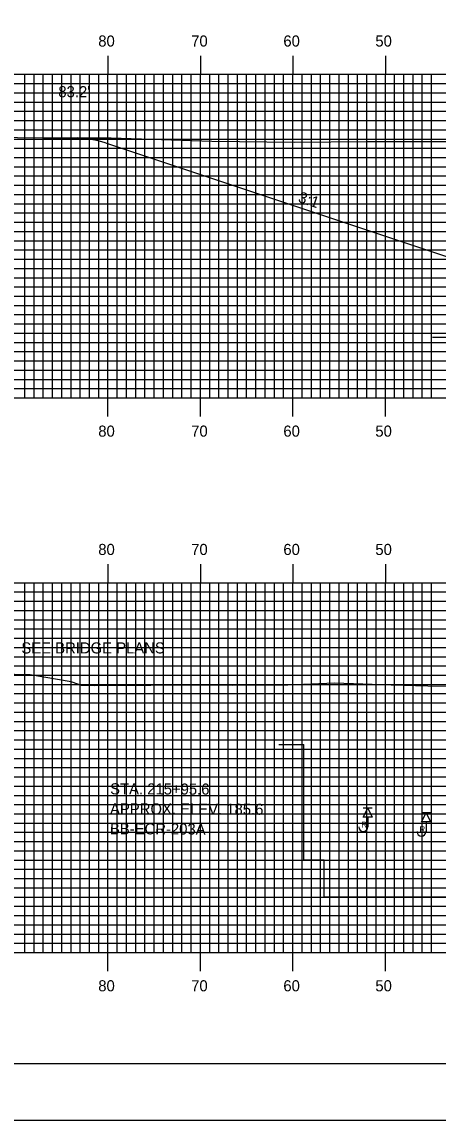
# Model space of a CAD drawing. Extents: x 1796420 to 1796763, y 442591 to 442811.
# Drawn here: x 1796496.6 to 1796541.6, y 442590.5 to 442709.3 of the extents above; entities that cross this region are included whole.
import ezdxf

# ---------------------------------------------------------------- set-up
doc = ezdxf.new("R2010")
doc.units = 0
for name, color, linetype in [('ANNOTATION', 7, 'Continuous'), ('BORDER', 7, 'Continuous'), ('BORING - REFUSAL', 7, 'Continuous'), ('D_Roadway_SlopeLines', 7, 'Continuous'), ('D_Text_Standard', 7, 'Continuous'), ('H_V ANNOTATION', 7, 'Continuous'), ('MAJOR', 7, 'Continuous'), ('MINOR', 7, 'Continuous'), ('PDRAIN', 7, 'Continuous'), ('PLOT BOUNDARY', 7, 'Continuous'), ('S_Roadway_Centerline', 7, 'Continuous')]:
    doc.layers.add(name, color=color, linetype=linetype)

msp = doc.modelspace()

# ---------------------------------------------------------------- linework, layer by layer
at = {"layer": 'ANNOTATION'}
for p, q in [((1796527.11, 442618.67), (1796527.11, 442631.17)), ((1796529.31, 442618.67), (1796527.11, 442618.67)), ((1796529.31, 442614.67), (1796529.31, 442618.67)), ((1796551.73, 442614.67), (1796529.31, 442614.67))]:
    msp.add_line(p, q, dxfattribs=at)
msp.add_lwpolyline([(1796524.4, 442631.17), (1796527.11, 442631.17)], dxfattribs=at)
at = {"layer": 'BORDER'}
msp.add_lwpolyline([(1796436.31, 442596.67), (1796756.31, 442596.67), (1796756.31, 442806.67), (1796436.31, 442806.67)], close=True, dxfattribs=at)
at = {"layer": 'BORING - REFUSAL'}
for p, q in [((1796534.49, 442624.27), (1796533.53, 442624.27)), ((1796534.01, 442623.31), (1796534.01, 442622.25)), ((1796540.79, 442623.77), (1796539.83, 442623.77)), ((1796540.31, 442622.81), (1796540.31, 442621.75))]:
    msp.add_line(p, q, dxfattribs=at)
for points in [[(1796534.01, 442624.27), (1796534.49, 442623.31), (1796533.53, 442623.31)], [(1796540.31, 442623.77), (1796540.79, 442622.81), (1796539.83, 442622.81)]]:
    msp.add_lwpolyline(points, close=True, dxfattribs=at)
for centre in [(1796533.52, 442622.25), (1796539.82, 442621.75)]:
    msp.add_arc(centre, 0.485, 180, 0, dxfattribs=at)
at = {"layer": 'D_Roadway_SlopeLines'}
msp.add_lwpolyline([(1796549.65, 442683.57), (1796543.65, 442683.57), (1796505.9, 442696.15)], dxfattribs=at)
msp.add_arc((1796501.86, 442684.01), 12.8, 71.5651, 86.7573, dxfattribs=at)
at = {"layer": 'MAJOR'}
for p, q in [((1796505.91, 442705.67), (1796505.91, 442703.67)), ((1796515.91, 442705.67), (1796515.91, 442703.67)), ((1796525.91, 442705.67), (1796525.91, 442703.67)), ((1796535.91, 442705.67), (1796535.91, 442703.67)), ((1796445.91, 442703.67), (1796725.91, 442703.67)), ((1796445.91, 442703.67), (1796725.91, 442703.67)), ((1796505.91, 442668.67), (1796505.91, 442703.67)), ((1796515.91, 442668.67), (1796515.91, 442703.67)), ((1796525.91, 442668.67), (1796525.91, 442703.67)), ((1796535.91, 442668.67), (1796535.91, 442703.67)), ((1796445.91, 442698.67), (1796725.91, 442698.67)), ((1796445.91, 442693.67), (1796725.91, 442693.67)), ((1796445.91, 442688.67), (1796725.91, 442688.67)), ((1796445.91, 442683.67), (1796725.91, 442683.67)), ((1796445.91, 442678.67), (1796725.91, 442678.67)), ((1796445.91, 442673.67), (1796725.91, 442673.67)), ((1796445.91, 442668.67), (1796725.91, 442668.67)), ((1796445.91, 442668.67), (1796725.91, 442668.67)), ((1796505.91, 442666.66), (1796505.91, 442668.67)), ((1796515.91, 442666.66), (1796515.91, 442668.67)), ((1796525.91, 442666.66), (1796525.91, 442668.67)), ((1796535.91, 442666.66), (1796535.91, 442668.67)), ((1796505.91, 442650.67), (1796505.91, 442648.67)), ((1796515.91, 442650.67), (1796515.91, 442648.67)), ((1796525.91, 442650.67), (1796525.91, 442648.67)), ((1796535.91, 442650.67), (1796535.91, 442648.67)), ((1796445.91, 442648.67), (1796725.91, 442648.67)), ((1796445.91, 442648.67), (1796725.91, 442648.67)), ((1796505.91, 442608.67), (1796505.91, 442648.67)), ((1796515.91, 442608.67), (1796515.91, 442648.67)), ((1796525.91, 442608.67), (1796525.91, 442648.67)), ((1796535.91, 442608.67), (1796535.91, 442648.67)), ((1796445.91, 442643.67), (1796725.91, 442643.67)), ((1796445.91, 442638.67), (1796725.91, 442638.67)), ((1796445.91, 442633.67), (1796725.91, 442633.67)), ((1796445.91, 442628.67), (1796725.91, 442628.67)), ((1796445.91, 442623.67), (1796725.91, 442623.67)), ((1796445.91, 442618.67), (1796725.91, 442618.67)), ((1796445.91, 442613.67), (1796725.91, 442613.67)), ((1796445.91, 442608.67), (1796725.91, 442608.67)), ((1796445.91, 442608.67), (1796725.91, 442608.67)), ((1796505.91, 442606.66), (1796505.91, 442608.67)), ((1796515.91, 442606.66), (1796515.91, 442608.67)), ((1796525.91, 442606.66), (1796525.91, 442608.67)), ((1796535.91, 442606.66), (1796535.91, 442608.67))]:
    msp.add_line(p, q, dxfattribs=at)
at = {"layer": 'MINOR'}
for p, q in [((1796445.91, 442702.67), (1796725.91, 442702.67)), ((1796496.91, 442668.67), (1796496.91, 442703.67)), ((1796497.91, 442668.67), (1796497.91, 442703.67)), ((1796498.91, 442668.67), (1796498.91, 442703.67)), ((1796499.91, 442668.67), (1796499.91, 442703.67)), ((1796500.91, 442668.67), (1796500.91, 442703.67)), ((1796501.91, 442668.67), (1796501.91, 442703.67)), ((1796502.91, 442668.67), (1796502.91, 442703.67)), ((1796503.91, 442668.67), (1796503.91, 442703.67)), ((1796504.91, 442668.67), (1796504.91, 442703.67)), ((1796506.91, 442668.67), (1796506.91, 442703.67)), ((1796507.91, 442668.67), (1796507.91, 442703.67)), ((1796508.91, 442668.67), (1796508.91, 442703.67)), ((1796509.91, 442668.67), (1796509.91, 442703.67)), ((1796510.91, 442668.67), (1796510.91, 442703.67)), ((1796511.91, 442668.67), (1796511.91, 442703.67)), ((1796512.91, 442668.67), (1796512.91, 442703.67)), ((1796513.91, 442668.67), (1796513.91, 442703.67)), ((1796514.91, 442668.67), (1796514.91, 442703.67)), ((1796516.91, 442668.67), (1796516.91, 442703.67)), ((1796517.91, 442668.67), (1796517.91, 442703.67)), ((1796518.91, 442668.67), (1796518.91, 442703.67)), ((1796519.91, 442668.67), (1796519.91, 442703.67)), ((1796520.91, 442668.67), (1796520.91, 442703.67)), ((1796521.91, 442668.67), (1796521.91, 442703.67)), ((1796522.91, 442668.67), (1796522.91, 442703.67)), ((1796523.91, 442668.67), (1796523.91, 442703.67)), ((1796524.91, 442668.67), (1796524.91, 442703.67)), ((1796526.91, 442668.67), (1796526.91, 442703.67)), ((1796527.91, 442668.67), (1796527.91, 442703.67)), ((1796528.91, 442668.67), (1796528.91, 442703.67)), ((1796529.91, 442668.67), (1796529.91, 442703.67)), ((1796530.91, 442668.67), (1796530.91, 442703.67)), ((1796531.91, 442668.67), (1796531.91, 442703.67)), ((1796532.91, 442668.67), (1796532.91, 442703.67)), ((1796533.91, 442668.67), (1796533.91, 442703.67)), ((1796534.91, 442668.67), (1796534.91, 442703.67)), ((1796536.91, 442668.67), (1796536.91, 442703.67)), ((1796537.91, 442668.67), (1796537.91, 442703.67)), ((1796538.91, 442668.67), (1796538.91, 442703.67)), ((1796539.91, 442668.67), (1796539.91, 442703.67)), ((1796540.91, 442668.67), (1796540.91, 442703.67)), ((1796445.91, 442701.67), (1796725.91, 442701.67)), ((1796445.91, 442700.67), (1796725.91, 442700.67)), ((1796445.91, 442699.67), (1796725.91, 442699.67)), ((1796445.91, 442697.67), (1796725.91, 442697.67)), ((1796445.91, 442696.67), (1796725.91, 442696.67)), ((1796445.91, 442695.67), (1796725.91, 442695.67)), ((1796445.91, 442694.67), (1796725.91, 442694.67)), ((1796445.91, 442692.67), (1796725.91, 442692.67)), ((1796445.91, 442691.67), (1796725.91, 442691.67)), ((1796445.91, 442690.67), (1796725.91, 442690.67)), ((1796445.91, 442689.67), (1796725.91, 442689.67)), ((1796445.91, 442687.67), (1796725.91, 442687.67)), ((1796445.91, 442686.67), (1796725.91, 442686.67)), ((1796445.91, 442685.67), (1796725.91, 442685.67)), ((1796445.91, 442684.67), (1796725.91, 442684.67)), ((1796445.91, 442682.67), (1796725.91, 442682.67)), ((1796445.91, 442681.67), (1796725.91, 442681.67)), ((1796445.91, 442680.67), (1796725.91, 442680.67)), ((1796445.91, 442679.67), (1796725.91, 442679.67)), ((1796445.91, 442677.67), (1796725.91, 442677.67)), ((1796445.91, 442676.67), (1796725.91, 442676.67)), ((1796445.91, 442675.67), (1796725.91, 442675.67)), ((1796445.91, 442674.67), (1796725.91, 442674.67)), ((1796445.91, 442672.67), (1796725.91, 442672.67)), ((1796445.91, 442671.67), (1796725.91, 442671.67)), ((1796445.91, 442670.67), (1796725.91, 442670.67)), ((1796445.91, 442669.67), (1796725.91, 442669.67)), ((1796496.91, 442608.67), (1796496.91, 442648.67)), ((1796497.91, 442608.67), (1796497.91, 442648.67)), ((1796498.91, 442608.67), (1796498.91, 442648.67)), ((1796499.91, 442608.67), (1796499.91, 442648.67)), ((1796500.91, 442608.67), (1796500.91, 442648.67)), ((1796501.91, 442608.67), (1796501.91, 442648.67)), ((1796502.91, 442608.67), (1796502.91, 442648.67)), ((1796503.91, 442608.67), (1796503.91, 442648.67)), ((1796504.91, 442608.67), (1796504.91, 442648.67)), ((1796506.91, 442608.67), (1796506.91, 442648.67)), ((1796507.91, 442608.67), (1796507.91, 442648.67)), ((1796508.91, 442608.67), (1796508.91, 442648.67)), ((1796509.91, 442608.67), (1796509.91, 442648.67)), ((1796510.91, 442608.67), (1796510.91, 442648.67)), ((1796511.91, 442608.67), (1796511.91, 442648.67)), ((1796512.91, 442608.67), (1796512.91, 442648.67)), ((1796513.91, 442608.67), (1796513.91, 442648.67)), ((1796514.91, 442608.67), (1796514.91, 442648.67)), ((1796516.91, 442608.67), (1796516.91, 442648.67)), ((1796517.91, 442608.67), (1796517.91, 442648.67)), ((1796518.91, 442608.67), (1796518.91, 442648.67)), ((1796519.91, 442608.67), (1796519.91, 442648.67)), ((1796520.91, 442608.67), (1796520.91, 442648.67)), ((1796521.91, 442608.67), (1796521.91, 442648.67)), ((1796522.91, 442608.67), (1796522.91, 442648.67)), ((1796523.91, 442608.67), (1796523.91, 442648.67)), ((1796524.91, 442608.67), (1796524.91, 442648.67)), ((1796526.91, 442608.67), (1796526.91, 442648.67)), ((1796527.91, 442608.67), (1796527.91, 442648.67)), ((1796528.91, 442608.67), (1796528.91, 442648.67)), ((1796529.91, 442608.67), (1796529.91, 442648.67)), ((1796530.91, 442608.67), (1796530.91, 442648.67)), ((1796531.91, 442608.67), (1796531.91, 442648.67)), ((1796532.91, 442608.67), (1796532.91, 442648.67)), ((1796533.91, 442608.67), (1796533.91, 442648.67)), ((1796534.91, 442608.67), (1796534.91, 442648.67)), ((1796536.91, 442608.67), (1796536.91, 442648.67)), ((1796537.91, 442608.67), (1796537.91, 442648.67)), ((1796538.91, 442608.67), (1796538.91, 442648.67)), ((1796539.91, 442608.67), (1796539.91, 442648.67)), ((1796540.91, 442608.67), (1796540.91, 442648.67)), ((1796445.91, 442647.67), (1796725.91, 442647.67)), ((1796445.91, 442646.67), (1796725.91, 442646.67)), ((1796445.91, 442645.67), (1796725.91, 442645.67)), ((1796445.91, 442644.67), (1796725.91, 442644.67)), ((1796445.91, 442642.67), (1796725.91, 442642.67)), ((1796445.91, 442641.67), (1796725.91, 442641.67)), ((1796445.91, 442640.67), (1796725.91, 442640.67)), ((1796445.91, 442639.67), (1796725.91, 442639.67)), ((1796445.91, 442637.67), (1796725.91, 442637.67)), ((1796445.91, 442636.67), (1796725.91, 442636.67)), ((1796445.91, 442635.67), (1796725.91, 442635.67)), ((1796445.91, 442634.67), (1796725.91, 442634.67)), ((1796445.91, 442632.67), (1796725.91, 442632.67)), ((1796445.91, 442631.67), (1796725.91, 442631.67)), ((1796445.91, 442630.67), (1796725.91, 442630.67)), ((1796445.91, 442629.67), (1796725.91, 442629.67)), ((1796445.91, 442627.67), (1796725.91, 442627.67)), ((1796445.91, 442626.67), (1796725.91, 442626.67)), ((1796445.91, 442625.67), (1796725.91, 442625.67)), ((1796445.91, 442624.67), (1796725.91, 442624.67)), ((1796445.91, 442622.67), (1796725.91, 442622.67)), ((1796445.91, 442621.67), (1796725.91, 442621.67)), ((1796445.91, 442620.67), (1796725.91, 442620.67)), ((1796445.91, 442619.67), (1796725.91, 442619.67)), ((1796445.91, 442617.67), (1796725.91, 442617.67)), ((1796445.91, 442616.67), (1796725.91, 442616.67)), ((1796445.91, 442615.67), (1796725.91, 442615.67)), ((1796445.91, 442614.67), (1796725.91, 442614.67)), ((1796445.91, 442612.67), (1796725.91, 442612.67)), ((1796445.91, 442611.67), (1796725.91, 442611.67)), ((1796445.91, 442610.67), (1796725.91, 442610.67)), ((1796445.91, 442609.67), (1796725.91, 442609.67))]:
    msp.add_line(p, q, dxfattribs=at)
at = {"layer": 'PDRAIN'}
msp.add_line((1796541.01, 442675.25), (1796551.73, 442675.25), dxfattribs=at)
at = {"layer": 'PLOT BOUNDARY'}
msp.add_lwpolyline([(1796420.12, 442590.55), (1796760.12, 442590.55), (1796760.12, 442810.55), (1796420.12, 442810.55)], close=True, dxfattribs=at)
at = {"layer": 'S_Roadway_Centerline'}
for points in [[(1796487.88, 442696.94), (1796498.86, 442696.78), (1796506.27, 442696.78), (1796517.15, 442696.43), (1796526.08, 442696.33), (1796533.98, 442696.39), (1796545.59, 442696.39), (1796546.1, 442696.39), (1796557.91, 442696.42), (1796565.89, 442696.24), (1796575.55, 442696.1), (1796585.62, 442695.94), (1796593.15, 442695.94), (1796604.73, 442695.91), (1796605.08, 442695.91), (1796605.32, 442695.91), (1796616.8, 442695.87), (1796625.5, 442695.88), (1796628.63, 442695.82), (1796633.06, 442695.87)], [(1796494.5, 442638.83), (1796497.11, 442638.76), (1796497.48, 442638.74), (1796501.91, 442637.97), (1796502.01, 442637.95), (1796503.02, 442637.6), (1796504.43, 442637.55), (1796516.66, 442637.64), (1796517.92, 442637.62), (1796519.38, 442637.59), (1796521.1, 442637.62), (1796525.37, 442637.62), (1796530.41, 442637.83), (1796536.54, 442637.62), (1796540.51, 442637.5), (1796559.84, 442637.32)]]:
    msp.add_lwpolyline(points, dxfattribs=at)

# ---------------------------------------------------------------- texts
at = {"layer": 'ANNOTATION'}
msp.add_text('3:1', height=1.2, rotation=341.5651, dxfattribs=at).set_placement((1796526.4, 442689.88))
msp.add_text('3:1', height=1.2, rotation=341.5651, dxfattribs=at).set_placement((1796526.4, 442689.88))
msp.add_text('SEE BRIDGE PLANS', height=1.2, dxfattribs=at).set_placement((1796496.54, 442641.02))
at = {"layer": 'BORING - REFUSAL'}
for s, p in [('STA. 215+95.6', (1796506.14, 442625.78)), ('APPROX. ELEV. 185.6', (1796506.13, 442623.62)), ('BB-ECR-203A', (1796506.12, 442621.46))]:
    msp.add_text(s, height=1.2, rotation=359.8142, dxfattribs=at).set_placement(p)
for p in [(1796533.3, 442622.19), (1796539.6, 442621.69)]:
    msp.add_text('R', height=0.64, dxfattribs=at).set_placement(p)
at = {"layer": 'D_Text_Standard'}
msp.add_text("83.2'", height=1.2, dxfattribs=at).set_placement((1796500.54, 442701.19))
at = {"layer": 'H_V ANNOTATION'}
for s, p in [('80', (1796504.86, 442706.67)), ('70', (1796514.91, 442706.67)), ('60', (1796524.88, 442706.67)), ('50', (1796534.83, 442706.67)), ('80', (1796504.86, 442664.47)), ('70', (1796514.91, 442664.47)), ('60', (1796524.88, 442664.47)), ('50', (1796534.83, 442664.47)), ('80', (1796504.86, 442651.67)), ('70', (1796514.91, 442651.67)), ('60', (1796524.88, 442651.67)), ('50', (1796534.83, 442651.67)), ('80', (1796504.86, 442604.47)), ('70', (1796514.91, 442604.47)), ('60', (1796524.88, 442604.47)), ('50', (1796534.83, 442604.47))]:
    msp.add_text(s, height=1.2, dxfattribs=at).set_placement(p)

doc.saveas('drawing.dxf')
